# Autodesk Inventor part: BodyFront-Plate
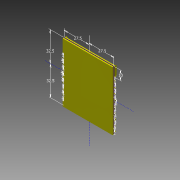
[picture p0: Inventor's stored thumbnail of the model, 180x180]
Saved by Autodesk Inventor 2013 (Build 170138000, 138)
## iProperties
Created: 2013-04
Part Number: BodyFront-Plate
Material: Generic
Document SubType Name: Modeling
Designer: frankenteddy
Density: 1 g/cm^3
Author: frankenteddy
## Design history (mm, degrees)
sketch "Sketch1"
  geometry: L1 (0, -5.555)-(-4.811, -2.778); L2 (0, -16.988)-(27.5, 32.5); L3 (27.5, 32.5)-(-27.5, 32.5); L4 (27.5, 32.5)-(-27.5, 32.5); L5 (27.5, 32.5)-(27.5, -32.5); L6 (-27.5, -28.5)-(27.5, -28.5); L7 (-27.5, -30.5)-(27.5, -30.5); L8 (-27.5, -32.5)-(27.5, -32.5); L9 (-27.5, -32.5)-(27.5, -32.5); L10 (-27.5, 32.5)-(0, -16.988); L11 (-27.5, -32.5)-(-27.5, 32.5); L12 (4.811, -2.778)-(0, -5.555); L13 (-0.599, -7.035)-(-5.567, -4.167); L14 (-5.567, -4.167)-(-0.599, -13.107); L15 (-0.599, -13.107)-(-0.599, -7.035); L16 (5.828, -16.5)-(27.5, -16.5); L17 (4.717, -18.5)-(27.5, -18.5); L18 (1.383, -24.5)-(27.5, -24.5); L19 (2.494, -22.5)-(27.5, -22.5); L20 (4.811, 2.778)-(4.811, -2.778); L21 (0, 5.555)-(4.811, 2.778); L22 (-4.811, 2.778)-(0, 5.555); L23 (-6.043, 4.026)-(-1.897, 6.33); L24 (9.483, 12.641)-(0, 7.166); L25 (0, 7.166)-(-9.483, 12.641); L26 (-4.811, -2.778)-(-4.811, 2.778); L27 (9.483, 23.59)-(9.483, 12.641); L28 (-20.169, 24.247)-(-9.237, 4.573); L29 (-27.5, 32.5)-(-27.5, 22.5); L30 (-9.483, 12.641)-(-9.483, 23.59); L31 (-9.483, 23.59)-(0, 29.065); L32 (-11.042, 12.641)-(-11.042, 18.977); L33 (-11.042, 21.81)-(-11.042, 24.923); L34 (-11.042, 24.923)-(-7.433, 27.007); L35 (-4.231, 29.042)-(-1.487, 31.668); L36 (-11.042, 18.977)-(-20.169, 24.247); L37 (-1.487, 31.668)-(-24.867, 31.668); L38 (-24.867, 31.668)-(-4.231, 29.042); L39 (-7.433, 27.007)-(-23.608, 29.065); L40 (-23.608, 29.065)-(-11.042, 21.81); L41 (-6.043, 0)-(-6.043, 4.026); L42 (-9.237, 10.567)-(-7.433, 2.5); L43 (-9.237, 4.573)-(-11.042, 12.641); L44 (-7.433, 2.5)-(-6.043, 0); L45 (-27.5, 13.5)-(-22.499, 13.5); L46 (-27.5, 17.5)-(-24.722, 17.5); L47 (-1.897, 6.33)-(-9.237, 10.567); L48 (0, 29.065)-(9.483, 23.59); L49 (-5.31, 15.05)-(-5.31, 21.181); L50 (-5.31, 21.181)-(0, 24.247); L51 (0, 11.984)-(-5.31, 15.05); L52 (0, 24.247)-(5.31, 21.181); L53 (5.31, 21.181)-(5.31, 15.05); L54 (5.31, 15.05)-(0, 11.984); L55 (-27.5, 11.5)-(-21.387, 11.5); L56 (-27.5, -6.5)-(-11.385, -6.5); L57 (-27.5, -4.5)-(-12.496, -4.5); L58 (-27.5, -0.5)-(-14.719, -0.5); L59 (-27.5, 1.5)-(-15.831, 1.5); L60 (-27.5, 5.5)-(-18.053, 5.5); L61 (-27.5, 7.5)-(-19.165, 7.5); L62 (-27.5, -10.5)-(-9.162, -10.5); L63 (-27.5, -16.5)-(-5.828, -16.5); L64 (-27.5, -18.5)-(-4.717, -18.5)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; C1 r 7.849 at (0, 18.116); 5 further points
  constraints: 162 end point, 33 parallel, 11 perpendicular, 8 horizontal, 4 point on line, 3 coincident, 2 collinear, 1 centre point, 1 vertical, 116 other
  dimensions: "d0" = 10 distance of L3.end L29.end; "d1" = 5 distance from line of L29.end L46; "d2" = 4 distance between parallel lines of L45 L46; "d3" = 2 distance between parallel lines of L55 L45; "d4" = 4 distance between parallel lines of L61 L55; "d5" = 2 distance between parallel lines of L60 L61; "d6" = 4 distance between parallel lines of L59 L60; "d7" = 2 distance between parallel lines of L58 L59; "d8" = 4 distance between parallel lines of L57 L58; "d9" = 2 distance between parallel lines of L56 L57; "d10" = 4 distance between parallel lines of L62 L56; "d11" = 2 distance between parallel lines of L67 L62; "d12" = 4 distance between parallel lines of L63 L67; "d13" = 2 distance between parallel lines of L64 L63; "d14" = 4 distance between parallel lines of L65 L64; "d15" = 2 distance between parallel lines of L66 L65; "d16" = 4 distance between parallel lines of L6 L66; "d17" = 2 distance between parallel lines of L7 L6; "d18" = 4 distance between parallel lines of L18 L6; "d19" = 2 distance between parallel lines of L18 L19; "d20" = 4 distance between parallel lines of L19 L17; "d21" = 2 distance between parallel lines of L17 L16; "d22" = 4 distance between parallel lines of L16 L73; "d23" = 2 distance between parallel lines of L73 L68; "d24" = 4 distance between parallel lines of L68 L69; "d25" = 2 distance between parallel lines of L69 L70; "d26" = 4 distance between parallel lines of L70 L71; "d27" = 2 distance between parallel lines of L71 L72; "d28" = 4 distance between parallel lines of L72 L75; "d29" = 2 distance between parallel lines of L75 L76; "d30" = 4 distance between parallel lines of L76 L77; "d31" = 2 distance between parallel lines of L77 L79; "d32" = 4 distance between parallel lines of L79 L78; "d33" = 32.5 distance between parallel lines of L80 L3; "d34" = 27.5 distance between parallel lines of L81 L5; "d35" = 27.5 distance between parallel lines of L11 L81; "d36" = 32.5 distance between parallel lines of L80 L8
sketch "Sketch2"
  geometry: L1 (-27.5, 32.5)-(27.5, 32.5); L2 (27.5, 32.5)-(27.5, -32.5); L3 (27.5, -32.5)-(-27.5, -32.5); L4 (-27.5, -32.5)-(-27.5, 32.5); 3 further points
  constraints: 8 end point, 2 midpoint, 2 parallel, 1 horizontal, 1 horizontal alignment, 1 perpendicular, 1 vertical alignment
  dimensions: "d37" = 55 distance of L2.end L3.end; "d38" = 65 distance of L1.end L2.end
extrude "Extrusion1" new body sketch "Sketch2" distance "d39" = 1.62; taper "d40" = 0 deg
extrude "Extrusion7" join sketch "Sketch1" distance "d51" = 1.5; taper "d52" = 0 deg
extrude "Extrusion2" join sketch "Sketch1" distance "d41" = 3; taper "d42" = 0 deg
extrude "Extrusion5" cut sketch "Sketch1" distance "d47" = 3; taper "d48" = 0 deg
extrude "Extrusion6" cut sketch "Sketch1" distance "d49" = 1.5; taper "d50" = 0 deg
mirror "Mirror1"
extrude "Extrusion8" join sketch "Sketch1" distance "d53" = 2; taper "d54" = 0 deg
chamfer "Chamfer1" distance "d55" = 2; stored, may be unused: second distance "d56" = 2, angle "d57" = 45 deg
body "Solid1"
